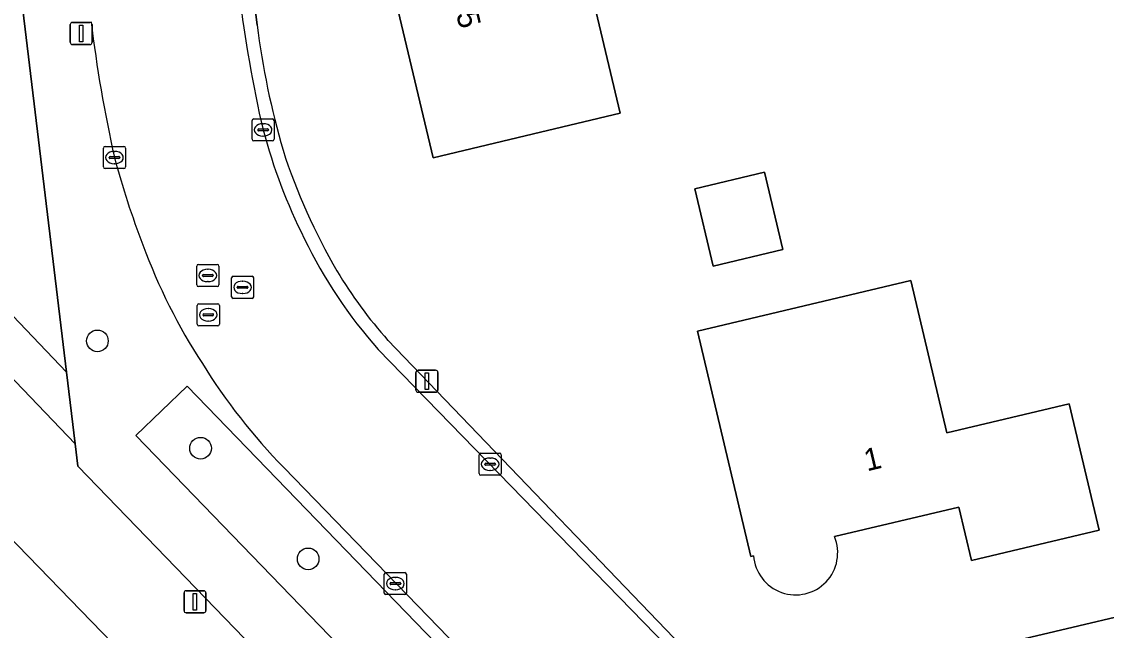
# Model space of a CAD drawing. Extents: x 157648 to 158502, y 379212 to 380938.
# Drawn here: x 158088.06 to 158137.15, y 380376.46 to 380404 of the extents above; entities that cross this region are included whole.
import ezdxf

# ---------------------------------------------------------------- set-up
doc = ezdxf.new("R2010")
doc.units = 0
for name, color, linetype in [('IMGEO_Boom', 7, 'Continuous'), ('IMGEO_Erf', 7, 'Continuous'), ('IMGEO_Groenvoorziening', 7, 'Continuous'), ('IMGEO_Kolk', 7, 'Continuous'), ('IMGEO_Lichtmast', 7, 'Continuous'), ('IMGEO_Pand', 7, 'Continuous'), ('IMGEO_Pand_nummerreeks', 7, 'Continuous'), ('IMGEO_Rijbaan_lokaal_open', 7, 'Continuous'), ('IMGEO_Rioolput', 7, 'Continuous'), ('IMGEO_Voetpad_open', 7, 'Continuous')]:
    doc.layers.add(name, color=color, linetype=linetype)

msp = doc.modelspace()

# ---------------------------------------------------------------- linework, layer by layer
at = {"layer": 'IMGEO_Boom'}
for centre in [(158091.485, 380389.555), (158096.154, 380384.698), (158101.024, 380379.69)]:
    msp.add_circle(centre, 0.489, dxfattribs=at)
at = {"layer": 'IMGEO_Erf'}
for points in [[(158104.637, 380389.58), (158120.553, 380373.032), (158128.773, 380374.988), (158129.696, 380375.215), (158131.555, 380375.637), (158142.159, 380378.143), (158141.597, 380380.606), (158158.361, 380384.507), (158164.272, 380378.503), (158195.64, 380409.139), (158187.298, 380444.893)], [(158094.291, 380439.409), (158095.577, 380427.704), (158097.636, 380411.068), (158097.666, 380410.864), (158097.859, 380410.909), (158098.711, 380403.846)], [(158084.961, 380341.306), (158091.847, 380347.972), (158100.664, 380356.509), (158103.667, 380359.403), (158105.995, 380361.632), (158075.944, 380392.592)], [(158121.185, 380379.829), (158121.063, 380379.8), (158118.642, 380389.998), (158128.297, 380392.291), (158129.935, 380385.393), (158135.462, 380386.705)], [(158135.462, 380386.705), (158136.82, 380380.988), (158131.041, 380379.616), (158130.467, 380382.034), (158124.844, 380380.698)]]:
    msp.add_lwpolyline(points, dxfattribs=at)
for points in [[(158115.149, 380399.856), (158111.541, 380398.999), (158106.676, 380397.843), (158105.023, 380404.802), (158103.973, 380404.552), (158103.082, 380408.306), (158107.947, 380409.462), (158114.095, 380410.922), (158114.586, 380408.857), (158113.095, 380408.503)], [(158121.674, 380397.187), (158122.505, 380393.69), (158119.361, 380392.943), (158118.53, 380396.44)]]:
    msp.add_lwpolyline(points, close=True, dxfattribs=at)
for centre, radius, start, end in [((158136.289, 380408.68), 37.888, 187.3307, 196.0928), ((158126.304, 380406.73), 27.768, 197.9368, 210.2976), ((158119.953, 380403.252), 20.531, 210.8613, 221.7554), ((158123.085, 380379.967), 1.905, 184.1392, 22.5809)]:
    msp.add_arc(centre, radius, start, end, dxfattribs=at)
at = {"layer": 'IMGEO_Groenvoorziening'}
for points in [[(158087.71, 380407.928), (158078.805, 380399.971), (158090.083, 380388.142)], [(158095.545, 380387.499), (158093.226, 380385.279), (158111.192, 380366.685), (158113.544, 380368.914)]]:
    msp.add_lwpolyline(points, close=True, dxfattribs=at)
msp.add_lwpolyline([(158075.944, 380392.592), (158105.995, 380361.632), (158106.073, 380361.706), (158109.224, 380364.626), (158090.592, 380383.892), (158090.472, 380384.897), (158077.313, 380398.639)], dxfattribs=at)
at = {"layer": 'IMGEO_Kolk'}
for p, q in [((158098.483, 380398.675), (158098.483, 380399.527)), ((158098.558, 380399.601), (158099.41, 380399.601)), ((158098.971, 380399.381), (158098.996, 380399.381)), ((158099.484, 380399.527), (158099.484, 380398.675)), ((158098.742, 380399.095), (158098.742, 380399.107)), ((158099.18, 380399.058), (158098.782, 380399.058)), ((158098.785, 380399.144), (158099.183, 380399.144)), ((158098.994, 380398.821), (158098.969, 380398.821)), ((158099.226, 380399.107), (158099.226, 380399.095)), ((158091.756, 380397.424), (158091.756, 380398.276)), ((158091.831, 380398.35), (158092.683, 380398.35)), ((158092.757, 380398.276), (158092.757, 380397.424)), ((158099.41, 380398.601), (158098.558, 380398.601)), ((158092.015, 380397.844), (158092.015, 380397.856)), ((158092.453, 380397.807), (158092.055, 380397.807)), ((158092.058, 380397.893), (158092.456, 380397.893)), ((158092.244, 380398.13), (158092.269, 380398.13)), ((158092.499, 380397.856), (158092.499, 380397.844)), ((158092.683, 380397.35), (158091.831, 380397.35)), ((158092.267, 380397.57), (158092.242, 380397.57)), ((158108.835, 380384.475), (158109.687, 380384.475)), ((158108.76, 380383.549), (158108.76, 380384.401)), ((158109.062, 380384.018), (158109.46, 380384.018)), ((158109.248, 380384.255), (158109.273, 380384.255)), ((158109.761, 380384.401), (158109.761, 380383.549)), ((158109.019, 380383.969), (158109.019, 380383.981)), ((158109.457, 380383.932), (158109.059, 380383.932)), ((158109.271, 380383.695), (158109.246, 380383.695)), ((158109.503, 380383.981), (158109.503, 380383.969)), ((158109.687, 380383.475), (158108.835, 380383.475)), ((158104.469, 380378.147), (158104.469, 380378.999)), ((158104.544, 380379.073), (158105.396, 380379.073)), ((158104.771, 380378.616), (158105.169, 380378.616)), ((158104.957, 380378.853), (158104.982, 380378.853)), ((158105.47, 380378.999), (158105.47, 380378.147)), ((158104.728, 380378.567), (158104.728, 380378.579)), ((158105.166, 380378.53), (158104.768, 380378.53)), ((158104.98, 380378.293), (158104.955, 380378.293)), ((158105.212, 380378.579), (158105.212, 380378.567)), ((158105.396, 380378.073), (158104.544, 380378.073))]:
    msp.add_line(p, q, dxfattribs=at)
for points in [[(158098.483, 380398.675), (158098.483, 380399.527)], [(158098.558, 380399.601), (158099.41, 380399.601)], [(158099.484, 380399.527), (158099.484, 380398.675)], [(158091.756, 380397.424), (158091.756, 380398.276)], [(158091.831, 380398.35), (158092.683, 380398.35)], [(158092.757, 380398.276), (158092.757, 380397.424)], [(158099.41, 380398.601), (158098.558, 380398.601)], [(158092.683, 380397.35), (158091.831, 380397.35)], [(158108.835, 380384.475), (158109.687, 380384.475)], [(158108.76, 380383.549), (158108.76, 380384.401)], [(158109.761, 380384.401), (158109.761, 380383.549)], [(158109.687, 380383.475), (158108.835, 380383.475)], [(158104.469, 380378.147), (158104.469, 380378.999)], [(158104.544, 380379.073), (158105.396, 380379.073)], [(158105.47, 380378.999), (158105.47, 380378.147)], [(158105.396, 380378.073), (158104.544, 380378.073)]]:
    msp.add_lwpolyline(points, dxfattribs=at)
for centre, radius, start, end in [((158098.56, 380399.525), 0.0765, 91.552, 178.448), ((158098.56, 380399.525), 0.0765, 91.552, 178.448), ((158099.408, 380399.525), 0.0765, 1.552, 88.448), ((158099.408, 380399.525), 0.0765, 1.552, 88.448), ((158098.782, 380399.104), 0.0403, 85.8775, 175.7526), ((158098.779, 380399.094), 0.0366, 178.938, 274.7102), ((158099.183, 380399.101), 0.043, 264.8664, 352.4533), ((158099.187, 380399.106), 0.0386, 1.7309, 96.639), ((158091.833, 380398.274), 0.0765, 91.552, 178.448), ((158091.833, 380398.274), 0.0765, 91.552, 178.448), ((158092.681, 380398.274), 0.0765, 1.552, 88.448), ((158092.681, 380398.274), 0.0765, 1.552, 88.448), ((158098.56, 380398.677), 0.0765, 181.552, 268.448), ((158098.56, 380398.677), 0.0765, 181.552, 268.448), ((158099.408, 380398.677), 0.0765, 271.552, 358.448), ((158099.408, 380398.677), 0.0765, 271.552, 358.448), ((158092.055, 380397.853), 0.0403, 85.8775, 175.7526), ((158092.052, 380397.843), 0.0366, 178.938, 274.7102), ((158092.456, 380397.85), 0.043, 264.8664, 352.4533), ((158092.46, 380397.855), 0.0386, 1.7309, 96.639), ((158091.833, 380397.426), 0.0765, 181.552, 268.448), ((158091.833, 380397.426), 0.0765, 181.552, 268.448), ((158092.681, 380397.426), 0.0765, 271.552, 358.448), ((158092.681, 380397.426), 0.0765, 271.552, 358.448), ((158108.837, 380384.399), 0.0765, 91.552, 178.448), ((158108.837, 380384.399), 0.0765, 91.552, 178.448), ((158109.685, 380384.399), 0.0765, 1.552, 88.448), ((158109.685, 380384.399), 0.0765, 1.552, 88.448), ((158109.059, 380383.978), 0.0403, 85.8775, 175.7526), ((158109.464, 380383.98), 0.0386, 1.7309, 96.639), ((158108.837, 380383.551), 0.0765, 181.552, 268.448), ((158108.837, 380383.551), 0.0765, 181.552, 268.448), ((158109.056, 380383.968), 0.0366, 178.938, 274.7102), ((158109.46, 380383.975), 0.043, 264.8664, 352.4533), ((158109.685, 380383.551), 0.0765, 271.552, 358.448), ((158109.685, 380383.551), 0.0765, 271.552, 358.448), ((158104.546, 380378.997), 0.0765, 91.552, 178.448), ((158104.546, 380378.997), 0.0765, 91.552, 178.448), ((158104.768, 380378.576), 0.0403, 85.8775, 175.7526), ((158105.173, 380378.578), 0.0386, 1.7309, 96.639), ((158105.394, 380378.997), 0.0765, 1.552, 88.448), ((158105.394, 380378.997), 0.0765, 1.552, 88.448), ((158104.546, 380378.149), 0.0765, 181.552, 268.448), ((158104.546, 380378.149), 0.0765, 181.552, 268.448), ((158104.765, 380378.566), 0.0366, 178.938, 274.7102), ((158105.169, 380378.573), 0.043, 264.8664, 352.4533), ((158105.394, 380378.149), 0.0765, 271.552, 358.448), ((158105.394, 380378.149), 0.0765, 271.552, 358.448)]:
    msp.add_arc(centre, radius, start, end, dxfattribs=at)
for centre, major_axis, ratio, start_param, end_param in [((158098.97, 380399.101), (-0.387, 0.002), 0.722429, 4.712389, 7.853982), ((158098.995, 380399.101), (-0.39, 0.002), 0.717154, 1.570796, 4.712389), ((158092.243, 380397.85), (-0.387, 0.002), 0.722429, 4.712389, 7.853982), ((158092.268, 380397.85), (-0.39, 0.002), 0.717154, 1.570796, 4.712389), ((158109.247, 380383.975), (-0.387, 0.002), 0.722429, 4.712389, 7.853982), ((158109.272, 380383.975), (-0.39, 0.002), 0.717154, 1.570796, 4.712389), ((158104.956, 380378.573), (-0.387, 0.002), 0.722429, 4.712389, 7.853982), ((158104.981, 380378.573), (-0.39, 0.002), 0.717154, 1.570796, 4.712389)]:
    msp.add_ellipse(centre, major_axis=major_axis, ratio=ratio, start_param=start_param, end_param=end_param, dxfattribs=at)
at = {"layer": 'IMGEO_Lichtmast'}
for p, q in [((158090.258, 380403.064), (158090.258, 380403.864)), ((158090.258, 380403.864), (158090.258, 380403.064)), ((158090.358, 380403.964), (158091.148, 380403.964)), ((158091.148, 380403.964), (158090.358, 380403.964)), ((158091.248, 380403.864), (158091.248, 380403.064)), ((158091.248, 380403.064), (158091.248, 380403.864)), ((158091.148, 380402.964), (158090.358, 380402.964)), ((158090.358, 380402.964), (158091.148, 380402.964)), ((158105.904, 380387.328), (158105.904, 380388.128)), ((158105.904, 380388.128), (158105.904, 380387.328)), ((158106.004, 380388.228), (158106.794, 380388.228)), ((158106.794, 380388.228), (158106.004, 380388.228)), ((158106.894, 380388.128), (158106.894, 380387.328)), ((158106.894, 380387.328), (158106.894, 380388.128)), ((158106.794, 380387.228), (158106.004, 380387.228)), ((158106.004, 380387.228), (158106.794, 380387.228)), ((158095.405, 380377.351), (158095.405, 380378.151)), ((158095.405, 380378.151), (158095.405, 380377.351)), ((158095.505, 380378.251), (158096.295, 380378.251)), ((158096.295, 380378.251), (158095.505, 380378.251)), ((158096.395, 380378.151), (158096.395, 380377.351)), ((158096.395, 380377.351), (158096.395, 380378.151)), ((158096.295, 380377.251), (158095.505, 380377.251)), ((158095.505, 380377.251), (158096.295, 380377.251))]:
    msp.add_line(p, q, dxfattribs=at)
for points in [[(158090.678, 380403.839), (158090.828, 380403.839), (158090.828, 380403.089), (158090.678, 380403.089), (158090.678, 380403.839)], [(158106.324, 380388.103), (158106.474, 380388.103), (158106.474, 380387.353), (158106.324, 380387.353), (158106.324, 380388.103)], [(158095.825, 380378.126), (158095.975, 380378.126), (158095.975, 380377.376), (158095.825, 380377.376), (158095.825, 380378.126)]]:
    msp.add_lwpolyline(points, dxfattribs=at)
for centre, start, end in [((158090.358, 380403.864), 90, 180), ((158090.358, 380403.864), 90, 180), ((158091.148, 380403.864), 0, 90), ((158091.148, 380403.864), 360, 90), ((158090.358, 380403.064), 180, 270), ((158090.358, 380403.064), 180, 270), ((158091.148, 380403.064), 270, 0), ((158091.148, 380403.064), 270, 0), ((158106.004, 380388.128), 90, 180), ((158106.004, 380388.128), 90, 180), ((158106.794, 380388.128), 0, 90), ((158106.794, 380388.128), 360, 90), ((158106.004, 380387.328), 180, 270), ((158106.004, 380387.328), 180, 270), ((158106.794, 380387.328), 270, 0), ((158106.794, 380387.328), 270, 0), ((158095.505, 380378.151), 90, 180), ((158095.505, 380378.151), 90, 180), ((158096.295, 380378.151), 0, 90), ((158096.295, 380378.151), 360, 90), ((158095.505, 380377.351), 180, 270), ((158095.505, 380377.351), 180, 270), ((158096.295, 380377.351), 270, 0), ((158096.295, 380377.351), 270, 0)]:
    msp.add_arc(centre, 0.1, start, end, dxfattribs=at)
at = {"layer": 'IMGEO_Pand'}
for points in [[(158111.541, 380398.999), (158115.149, 380399.856), (158113.095, 380408.503), (158114.586, 380408.857), (158114.095, 380410.922), (158107.947, 380409.462), (158103.082, 380408.306), (158103.973, 380404.552), (158105.023, 380404.802), (158106.676, 380397.843)], [(158119.361, 380392.943), (158122.505, 380393.69), (158121.674, 380397.187), (158118.53, 380396.44)]]:
    msp.add_lwpolyline(points, close=True, dxfattribs=at)
msp.add_lwpolyline([(158124.844, 380380.698), (158130.467, 380382.034), (158131.041, 380379.616), (158136.82, 380380.988), (158135.462, 380386.705), (158129.935, 380385.393), (158128.297, 380392.291), (158118.642, 380389.998), (158121.063, 380379.8), (158121.185, 380379.829)], dxfattribs=at)
msp.add_arc((158123.085, 380379.967), 1.905, 184.1392, 22.5809, dxfattribs=at)
at = {"layer": 'IMGEO_Rijbaan_lokaal_open'}
for points in [[(158123.553, 380369.281), (158120.025, 380372.906), (158104.198, 380389.167)], [(158099.931, 380383.806), (158113.871, 380369.425), (158116.496, 380366.721), (158117.545, 380365.64), (158119.774, 380363.285)]]:
    msp.add_lwpolyline(points, dxfattribs=at)
for centre, radius, start, end in [((158157.406, 380412.481), 59.935, 186.91248, 192.89989), ((158152.231, 380411.317), 61.467, 186.83963, 192.65589), ((158124.376, 380405.932), 26.295, 195.057, 206.5297), ((158129.071, 380407.677), 38.103, 194.9454, 201.2012), ((158118.258, 380402.923), 26.308, 200.0661, 213.1665), ((158120.235, 380403.489), 21.501, 205.6342, 221.767), ((158119.925, 380403.249), 27.889, 211.8523, 224.1993)]:
    msp.add_arc(centre, radius, start, end, dxfattribs=at)
at = {"layer": 'IMGEO_Rioolput'}
for p, q in [((158095.983, 380392.089), (158095.983, 380392.941)), ((158096.058, 380393.015), (158096.91, 380393.015)), ((158096.984, 380392.941), (158096.984, 380392.089)), ((158096.242, 380392.509), (158096.242, 380392.521)), ((158096.68, 380392.472), (158096.282, 380392.472)), ((158096.285, 380392.558), (158096.683, 380392.558)), ((158096.471, 380392.795), (158096.496, 380392.795)), ((158096.726, 380392.521), (158096.726, 380392.509)), ((158097.556, 380391.551), (158097.556, 380392.403)), ((158097.631, 380392.477), (158098.483, 380392.477)), ((158098.557, 380392.403), (158098.557, 380391.551)), ((158096.91, 380392.015), (158096.058, 380392.015)), ((158096.494, 380392.235), (158096.469, 380392.235)), ((158097.815, 380391.971), (158097.815, 380391.983)), ((158098.253, 380391.934), (158097.855, 380391.934)), ((158097.858, 380392.02), (158098.256, 380392.02)), ((158098.044, 380392.257), (158098.069, 380392.257)), ((158098.299, 380391.983), (158098.299, 380391.971)), ((158098.483, 380391.477), (158097.631, 380391.477)), ((158098.067, 380391.697), (158098.042, 380391.697)), ((158096.003, 380390.308), (158096.003, 380391.16)), ((158096.078, 380391.234), (158096.93, 380391.234)), ((158096.491, 380391.014), (158096.516, 380391.014)), ((158097.004, 380391.16), (158097.004, 380390.308)), ((158096.262, 380390.728), (158096.262, 380390.74)), ((158096.7, 380390.691), (158096.302, 380390.691)), ((158096.305, 380390.777), (158096.703, 380390.777)), ((158096.514, 380390.454), (158096.489, 380390.454)), ((158096.746, 380390.74), (158096.746, 380390.728)), ((158096.93, 380390.234), (158096.078, 380390.234))]:
    msp.add_line(p, q, dxfattribs=at)
for points in [[(158095.983, 380392.089), (158095.983, 380392.941)], [(158096.058, 380393.015), (158096.91, 380393.015)], [(158096.984, 380392.941), (158096.984, 380392.089)], [(158097.556, 380391.551), (158097.556, 380392.403)], [(158097.631, 380392.477), (158098.483, 380392.477)], [(158098.557, 380392.403), (158098.557, 380391.551)], [(158096.91, 380392.015), (158096.058, 380392.015)], [(158098.483, 380391.477), (158097.631, 380391.477)], [(158096.003, 380390.308), (158096.003, 380391.16)], [(158096.078, 380391.234), (158096.93, 380391.234)], [(158097.004, 380391.16), (158097.004, 380390.308)], [(158096.93, 380390.234), (158096.078, 380390.234)]]:
    msp.add_lwpolyline(points, dxfattribs=at)
for centre, radius, start, end in [((158096.06, 380392.939), 0.0765, 91.552, 178.448), ((158096.06, 380392.939), 0.0765, 91.552, 178.448), ((158096.908, 380392.939), 0.0765, 1.552, 88.448), ((158096.908, 380392.939), 0.0765, 1.552, 88.448), ((158096.282, 380392.518), 0.0403, 85.8775, 175.7526), ((158096.279, 380392.508), 0.0366, 178.938, 274.7102), ((158096.683, 380392.515), 0.043, 264.8664, 352.4533), ((158096.687, 380392.52), 0.0386, 1.7309, 96.639), ((158097.633, 380392.401), 0.0765, 91.552, 178.448), ((158097.633, 380392.401), 0.0765, 91.552, 178.448), ((158098.481, 380392.401), 0.0765, 1.552, 88.448), ((158098.481, 380392.401), 0.0765, 1.552, 88.448), ((158096.06, 380392.091), 0.0765, 181.552, 268.448), ((158096.06, 380392.091), 0.0765, 181.552, 268.448), ((158096.908, 380392.091), 0.0765, 271.552, 358.448), ((158096.908, 380392.091), 0.0765, 271.552, 358.448), ((158097.855, 380391.98), 0.0403, 85.8775, 175.7526), ((158097.852, 380391.97), 0.0366, 178.938, 274.7102), ((158098.256, 380391.977), 0.043, 264.8664, 352.4533), ((158098.26, 380391.982), 0.0386, 1.7309, 96.639), ((158097.633, 380391.553), 0.0765, 181.552, 268.448), ((158097.633, 380391.553), 0.0765, 181.552, 268.448), ((158098.481, 380391.553), 0.0765, 271.552, 358.448), ((158098.481, 380391.553), 0.0765, 271.552, 358.448), ((158096.08, 380391.158), 0.0765, 91.552, 178.448), ((158096.08, 380391.158), 0.0765, 91.552, 178.448), ((158096.928, 380391.158), 0.0765, 1.552, 88.448), ((158096.928, 380391.158), 0.0765, 1.552, 88.448), ((158096.302, 380390.737), 0.0403, 85.8775, 175.7526), ((158096.299, 380390.727), 0.0366, 178.938, 274.7102), ((158096.703, 380390.734), 0.043, 264.8664, 352.4533), ((158096.707, 380390.739), 0.0386, 1.7309, 96.639), ((158096.08, 380390.31), 0.0765, 181.552, 268.448), ((158096.08, 380390.31), 0.0765, 181.552, 268.448), ((158096.928, 380390.31), 0.0765, 271.552, 358.448), ((158096.928, 380390.31), 0.0765, 271.552, 358.448)]:
    msp.add_arc(centre, radius, start, end, dxfattribs=at)
for centre, major_axis, ratio, start_param, end_param in [((158096.47, 380392.515), (-0.387, 0.002), 0.722429, 4.712389, 7.853982), ((158096.495, 380392.515), (-0.39, 0.002), 0.717154, 1.570796, 4.712389), ((158098.043, 380391.977), (-0.387, 0.002), 0.722429, 4.712389, 7.853982), ((158098.068, 380391.977), (-0.39, 0.002), 0.717154, 1.570796, 4.712389), ((158096.49, 380390.734), (-0.387, 0.002), 0.722429, 4.712389, 7.853982), ((158096.515, 380390.734), (-0.39, 0.002), 0.717154, 1.570796, 4.712389)]:
    msp.add_ellipse(centre, major_axis=major_axis, ratio=ratio, start_param=start_param, end_param=end_param, dxfattribs=at)
at = {"layer": 'IMGEO_Voetpad_open'}
for points in [[(158073.063, 380528.837), (158074.678, 380515.405), (158076.753, 380498.285), (158084.325, 380435.852), (158086.631, 380416.924), (158086.681, 380416.507), (158087.42, 380410.342), (158087.71, 380407.928), (158090.083, 380388.142), (158090.472, 380384.897), (158090.592, 380383.892), (158109.224, 380364.626), (158111.192, 380366.685), (158093.226, 380385.279), (158095.545, 380387.499), (158113.544, 380368.914), (158113.647, 380369.012), (158113.548, 380369.117), (158113.871, 380369.425), (158099.931, 380383.806)], [(158054.227, 380422.099), (158074.872, 380400.738), (158077.313, 380398.639), (158090.472, 380384.897), (158090.083, 380388.142), (158078.805, 380399.971), (158087.71, 380407.928)], [(158098.711, 380403.846), (158097.859, 380410.909), (158097.666, 380410.864), (158098.095, 380407.325), (158097.658, 380407.265), (158097.907, 380405.268)], [(158104.198, 380389.167), (158120.025, 380372.906), (158120.553, 380373.032), (158104.637, 380389.58)], [(158143.242, 380374.803), (158142.159, 380378.143), (158131.555, 380375.637), (158129.696, 380375.215), (158128.773, 380374.988), (158120.553, 380373.032), (158120.025, 380372.906), (158123.553, 380369.281)]]:
    msp.add_lwpolyline(points, dxfattribs=at)
for centre, radius, start, end in [((158157.406, 380412.481), 59.935, 186.91248, 192.89989), ((158152.231, 380411.317), 61.467, 186.83963, 192.65589), ((158136.289, 380408.68), 37.888, 187.3307, 196.0928), ((158124.376, 380405.932), 26.295, 195.057, 206.5297), ((158129.071, 380407.677), 38.103, 194.9454, 201.2012), ((158126.304, 380406.73), 27.768, 197.9368, 210.2976), ((158118.258, 380402.923), 26.308, 200.0661, 213.1665), ((158120.235, 380403.489), 21.501, 205.6342, 221.767), ((158119.953, 380403.252), 20.531, 210.8613, 221.7554), ((158119.925, 380403.249), 27.889, 211.8523, 224.1993)]:
    msp.add_arc(centre, radius, start, end, dxfattribs=at)

# ---------------------------------------------------------------- texts
at = {"layer": 'IMGEO_Pand_nummerreeks'}
for s, rotation, p in [('45', 283.3621, (158107.548, 380405.074)), ('1', 13.3634, (158126.315, 380383.648))]:
    msp.add_text(s, height=1, rotation=rotation, dxfattribs=at).set_placement(p)

doc.saveas('drawing.dxf')
